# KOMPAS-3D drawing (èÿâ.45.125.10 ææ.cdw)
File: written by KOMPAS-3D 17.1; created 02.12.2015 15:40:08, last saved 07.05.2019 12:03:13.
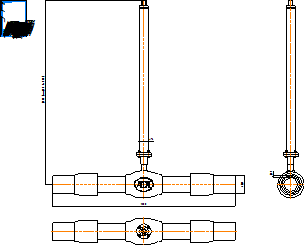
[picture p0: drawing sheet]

Sheet 1: A4, portrait

Title block, sheet 1: name: КШГ.45.125.10 СС; material: Внимание! Данный продукт является объектом авторского права ООО «Торговый Дом АДЛ». / Запрещается изменение, копирование, распространение / (в том числе путем копирования на другие сайты и ресурсы в Интернете) / или любое иное использование информации и объектов без предварительного / согласия правообладателя (ООО «Торговый Дом АДЛ»).; sheets: 1; organisation: ООО "Торговый дом АДЛ"; sheet format: A4; stored path: C:\Users\kka\KOMPAS_Work\Модели кранов для исследований\DN50\С удлинением\КШГ.32.050.40 СС ГЧ _ Шаровой кран БИВАЛ Ду50 Ру4 МПа редуцированный под приварку, с удлинением штока H=1100.cdw; drawn by: Климкович К.А.; drawn by, date: 07.12.16

Views: Вид 1, Проекционный вид 2
Referenced files in C:\Users\kka\KOMPAS_Work\Модели кранов для исследований\DN80\С удлинением\: КШТ.22.080.25 СС.a3d
Referenced files in C:\Users\kka\KOMPAS_Work\Модели кранов для исследований\DN150\С удлинением\: КШТ.22.150.25 СС.a3d, КШГ.35.125.25 СС Lстр600.a3d, КШГ.35.125.25 СС Lстр600.a3d!Деталь (локальная).m3d
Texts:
  Klimkovich
  ADL
  (от 480 до 5000)
Dimensions and other numbers on the sheet: 76; 140; 1500; 12,7; 1:1; 1; 07.12.16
